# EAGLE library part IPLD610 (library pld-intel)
PLD
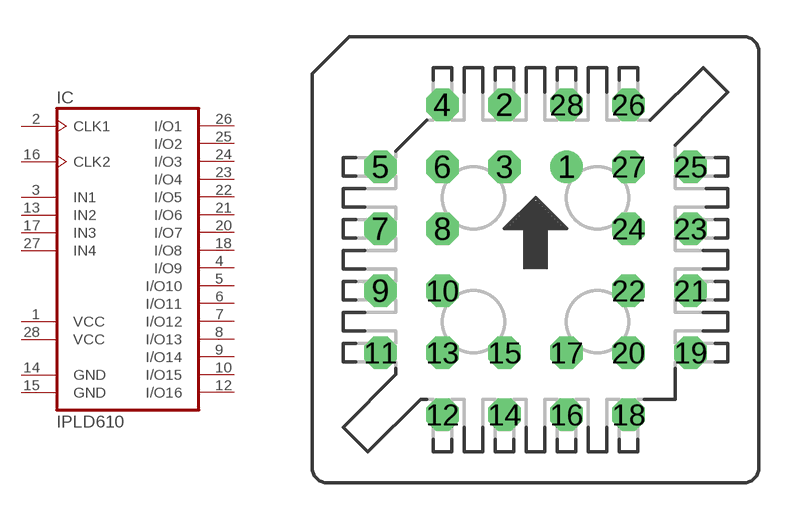
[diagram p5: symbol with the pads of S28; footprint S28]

Designator prefix IC

## IPLD610 (OC_FARNELL: unknown; OC_NEWARK: unknown)  [S28]
1  VCC  pwr
2  CLK1  in
3  IN1  in
4  I/O9
5  I/O10
6  I/O11
7  I/O12
8  I/O13
9  I/O14
10  I/O15
12  I/O16
13  IN2  in
14  GND  pwr
15  GND  pwr
16  CLK2  in
17  IN3  in
18  I/O8
20  I/O7
21  I/O6
22  I/O5
23  I/O4
24  I/O3
25  I/O2
26  I/O1
27  IN4  in
28  VCC  pwr

## Footprint S28 (pad centres in mm)
PLCC SOCKET
drill 0.813 round: 1 1.27,3.81
drill 0.813 octagon: 2 -1.27,6.35; 3 -1.27,3.81; 4 -3.81,6.35; 5 -6.35,3.81; 6 -3.81,3.81; 7 -6.35,1.27; 8 -3.81,1.27; 9 -6.35,-1.27; 10 -3.81,-1.27; 11 -6.35,-3.81; 12 -3.81,-6.35; 13 -3.81,-3.81; 14 -1.27,-6.35; 15 -1.27,-3.81; 16 1.27,-6.35; 17 1.27,-3.81; 18 3.81,-6.35; 19 6.35,-3.81; 20 3.81,-3.81; 21 6.35,-1.27; 22 3.81,-1.27; 23 6.35,1.27; 24 3.81,1.27; 25 6.35,3.81; 26 3.81,6.35; 27 3.81,3.81; 28 1.27,6.35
